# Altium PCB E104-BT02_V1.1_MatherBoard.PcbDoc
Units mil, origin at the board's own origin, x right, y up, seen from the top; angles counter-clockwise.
Board outline 2042.36 x 933 mil, 2 copper layers (Top Layer, Bottom Layer); 37 components, 30 nets, 137 pads, 131 vias.
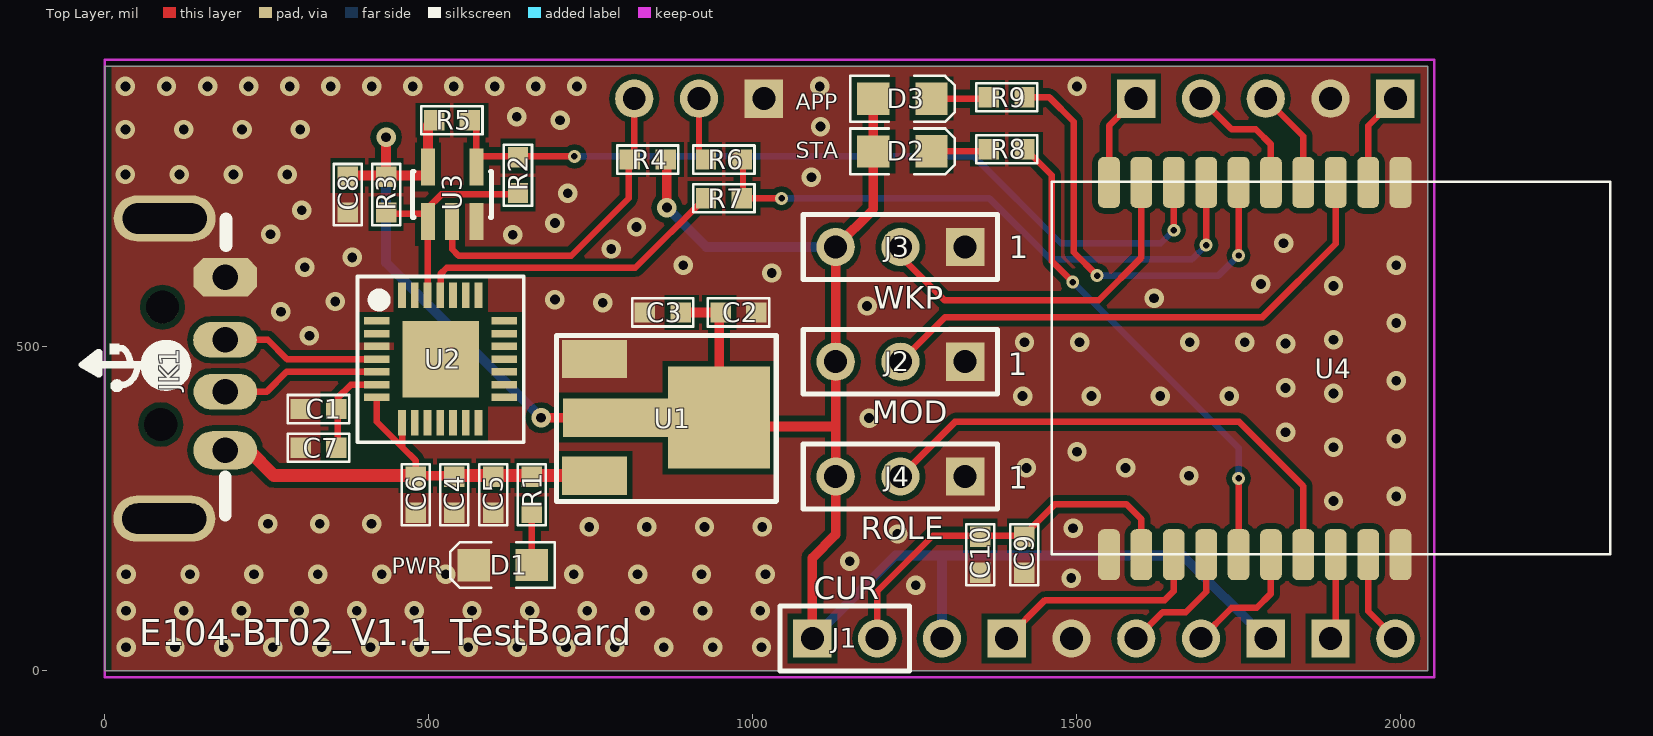
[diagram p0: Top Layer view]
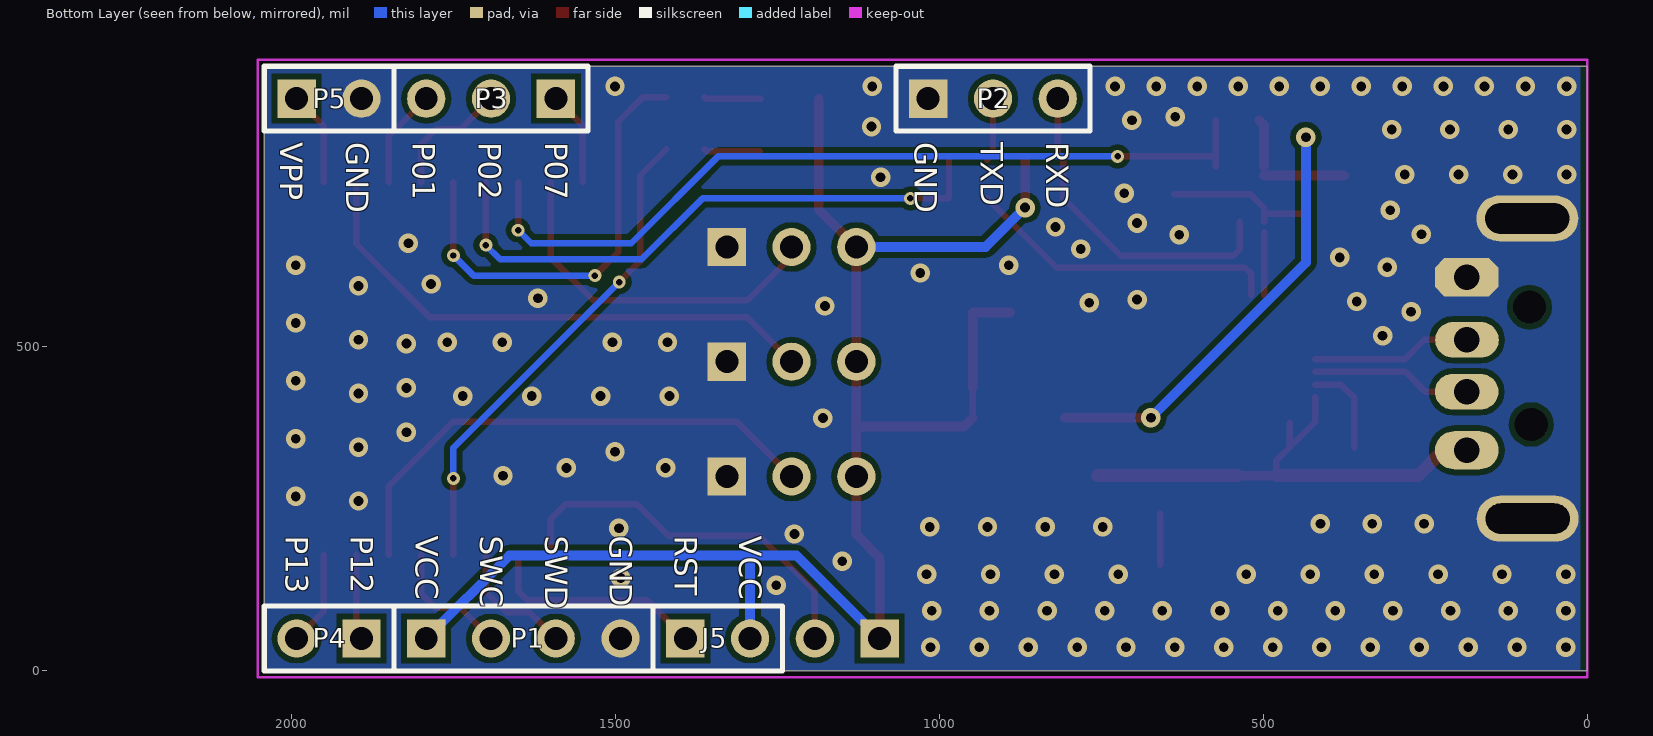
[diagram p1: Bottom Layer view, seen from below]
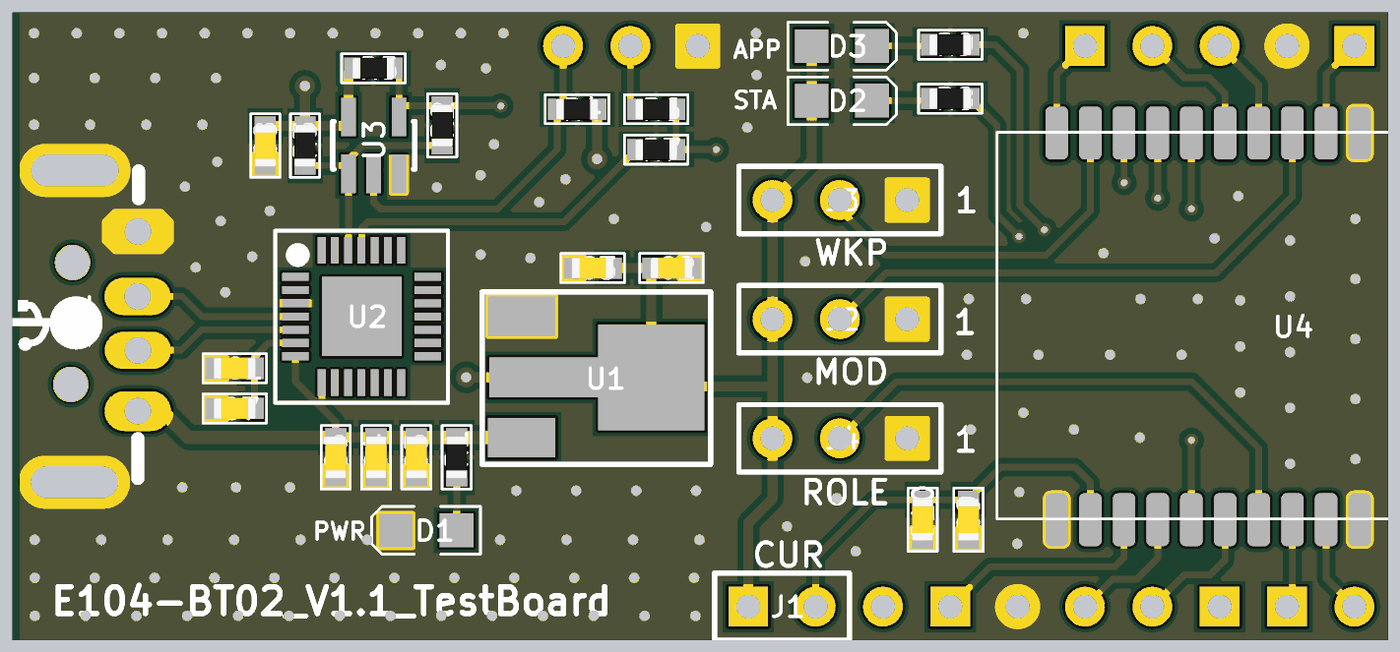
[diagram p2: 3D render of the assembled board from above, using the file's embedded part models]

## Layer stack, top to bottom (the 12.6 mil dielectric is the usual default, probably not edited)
Top Layer: signal copper 1.4
Dielectric: dielectric 12.6, FR-4, Dk 4.8
Bottom Layer: signal copper 1.4

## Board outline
0,0 0,933 2042.36,933 2042.36,0

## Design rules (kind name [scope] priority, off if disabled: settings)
Clearance [All] p1: gap=8.66
MinimumSolderMaskSliver [All] p1: minsoldermaskwidth=1
PolygonConnect [All] p1: connectstyle=Direct reliefconductorwidth=10 reliefentries=4 polygonreliefangle="90 Angle"
RoutingVias [All] p1: holewidth=28 width=50 viastyle="Through Hole" minholewidth=28 minwidth=50 maxholewidth=28 maxwidth=50
SilkToSilkClearance [All] p1: silktosilkclearance=1
SilkscreenOverComponentPads [All] p1: minsilkscreentomaskgap=1
SolderMaskExpansion [All] p1: expansion=4
Width [All] p1: maxlimit=20 minlimit=10 preferedwidth=10
25 further rules are at their usual default settings.

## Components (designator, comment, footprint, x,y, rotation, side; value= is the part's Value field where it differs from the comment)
C1 "10uF" CAP-0603 330.01,404 r180 top
C2 "10uF" CAP-0603 978.48,553 r0 top
C3 "0u1F" CAP-0603 861.48,553 r180 top
C4 "10uF" CAP-0603 539.83,271.6 r270 top
C5 "100nF" CAP-0603 599.66,271.6 r270 top
C6 "0u1F" CAP-0603 480.01,271.6 r270 top
C7 "0u1F" CAP-0603 330.01,344.18 r180 top
C8 "0u1F" CAP-0603 375.36,735 r90 top
C9 "0u1F" CAP-0603 1419.48,179 r270 top
C10 "1uF" CAP-0603 1351.48,179 r270 top
D1 "PWR_LED" LED0805 614.48,163 r180 top
D2 "GRE_LED" LED0805 1231.48,801.82 r0 top
D3 "RED_LED" LED0805 1231.48,883 r0 top
J1 "JMP2" HDR1X2 1142.48,49.68 r0 top
J2 "J_MOD" HDR1X3 1228.48,477 r180 top
J3 "J_WK" HDR1X3 1228.48,654.17 r180 top
J4 "J_ROLE" HDR1X3 1228.48,299.83 r180 top
J5 "J_RST" HDR1X2 1342.48,49.68 r180 bottom
JK1 "USB-A" USB-AG-DIP 136.36,466.4 r0 top
P1 "DBG" HDR1X4 1642.48,49.68 r180 bottom
P2 "EXT_UART" HDR1X3 917.48,883.13 r180 bottom
P3 "PIN0x" HDR1X3 1692.48,883.13 r0 bottom
P4 "PIN1x" HDR1X2 1942.48,49.68 r0 bottom
P5 "VPP" HDR1X2 1942.48,883.13 r180 bottom
R1 "1K" RES-0603 659.48,271.6 r270 top
R2 "NC" RES-0603 638,765 r270 top
R3 "10K" RES-0603 434.36,735 r90 top
R4 "10K" RES-0603 838.36,789.13 r180 top
R5 "NC" RES-0603 536,850 r0 top
R6 "120" RES-0603 955.88,789.13 r0 top
R7 "120" RES-0603 955.88,729.13 r180 top
R8 "1K" RES-0603 1392.48,804.82 r180 top
R9 "1K" RES-0603 1392.48,885 r180 top
U1 "AMS1117-3.3" SOT-223 852.36,391.13 r270 top
U2 "CP2102" QFN28-5X5-P0.5 518.48,481 r0 top
U3 "74LVC1G08" SOT23-5 536.36,693.13 r0 top
U4 "E104-BT02" E104-BT02_V1.1 1775.48,466.4 r270 top

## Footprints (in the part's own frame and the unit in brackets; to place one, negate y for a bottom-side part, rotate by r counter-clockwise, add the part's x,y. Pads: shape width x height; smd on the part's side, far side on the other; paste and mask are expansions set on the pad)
CAP-0603 [mm]
  rect 0.8x0.8 smd: 1(-0.7,0) 2(0.7,0)
  silkscreen extent -1.2,-0.55 1.2,0.55, body extent -0.8,-0.4 0.8,0.4, height 0.92
E104-BT02_V1.1 [mm]
  rrect50% 2x0.85 smd: 1(-7.3,5.715) 2(-7.3,4.445) 3(-7.3,3.175) 4(-7.3,1.905) 5(-7.3,0.635) 6(-7.3,-0.635) 7(-7.3,-1.905) 8(-7.3,-3.175) 9(-7.3,-4.445) 10(-7.3,-5.715) 11(7.3,-5.715) 12(7.3,-4.445) 13(7.3,-3.175) 14(7.3,-1.905) 15(7.3,-0.635) 16(7.3,0.635) 17(7.3,1.905) 18(7.3,3.175) 19(7.3,4.445) 20(7.3,5.715)
  silkscreen extent -7.33,-7.96 7.27,13.94
HDR1X2 [mm] "Connector; Header; 2 Position"
  rect 1.5x1.5 hole 0.9: 1(-1.27,0)
  round 1.5 hole 0.9: 2(1.27,0)
  silkscreen extent -2.54,-1.27 2.54,1.27
HDR1X3 [mm] "Connector; Header; 2 Position"
  rect 1.5x1.5 hole 0.9: 1(-2.54,0)
  round 1.5 hole 0.9: 2(0,0) 3(2.54,0)
  silkscreen extent -3.81,-1.27 3.81,1.27
HDR1X4 [mm] "Connector; Header; 2 Position"
  rect 1.5x1.5 hole 0.9: 1(-3.81,0)
  round 1.5 hole 0.9: 2(-1.27,0) 3(1.27,0) 4(3.81,0)
  silkscreen extent -5.08,-1.27 5.08,1.27
LED0805 [mil]
  rect 50x50 smd: A(-44.9,-0.18) K(44.9,0.18)
  silkscreen extent -80,-36 81,35
QFN28-5X5-P0.5 [mm]
  rect 3x3 smd: 0(0,0)
  rect 1x0.3 smd: 1(-2.5,1.5) 2(-2.5,1) 3(-2.5,0.5) 4(-2.5,0) 5(-2.5,-0.5) 6(-2.5,-1) 7(-2.5,-1.5) 15(2.5,-1.5) 16(2.5,-1) 17(2.5,-0.5) 18(2.5,0) 19(2.5,0.5) 20(2.5,1) 21(2.5,1.5)
  rect 0.3x1 smd: 8(-1.51,-2.5) 9(-1.01,-2.5) 10(-0.51,-2.5) 11(-0.01,-2.5) 12(0.49,-2.5) 13(0.99,-2.5) 14(1.49,-2.5) 22(1.49,2.5) 23(0.99,2.5) 24(0.49,2.5) 25(-0.01,2.5) 26(-0.51,2.5) 27(-1.01,2.5) 28(-1.51,2.5)
  silkscreen extent -3.26,-3.26 3.26,3.24
RES-0603 [mm]
  rect 0.8x0.8 smd: 1(-0.7,0) 2(0.7,0)
  silkscreen extent -1.2,-0.55 1.2,0.55, body extent -0.8,-0.4 0.8,0.4, height 0.5
SOT23-5 [mm]
  rect 0.55x1.45 smd: 1(-0.95,0) 2(0,0) 3(0.95,0) 4(0.95,2.15) 5(-0.95,2.15)
  silkscreen extent -1.55,0.18 1.55,1.98
SOT-223 [mm]
  rect 1.5x2.54 smd: 1(-2.29,-2.444) 3(2.29,-2.444)
  rect 4x4 smd: 2(0.013,2.444)
  rect 1.5x5.04 smd: 2(0.013,-1.156)
  silkscreen extent -3.21,-3.93 3.3,4.69
USB-AG-DIP [mm]
  oval 2.5x1.5 hole 1: 1(1.26,-3.202)
  oval 2.5x1.4 hole 1: 2(1.266,-0.909) 3(1.254,1.129)
  oct 2.5x1.5 hole 1: 4(1.266,3.581)
  oval 4x1.8 hole 1.2 slot 3.3 at 0 deg: 5(-1.127,-5.886) 6(-1.113,5.886)
  round 1.27 hole 1.3: 7(-1.198,2.41) 8(-1.266,-2.194)
  silkscreen extent -4.36,-5.74 1.29,5.87

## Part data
C1 C2 C3 C4 C5 C6 C7: library part cap0603, "Capacitor"
C8 C9 C10: library part Cap, "0603"
D1 D2 D3: library part LED
J2 J3 J4: library part JMP3
J5: library part JMP2
P1: library part "Header 4H", "Header, 4-Pin, Right Angle"
P2 P3: library part "Header 3H", "Header, 3-Pin, Right Angle"
P4 P5: library part "Header 2H", "Header, 2-Pin, Right Angle"
R1: library part res0603
R2 R3 R4 R5 R6 R7 R8 R9: library part Res2, "0603"

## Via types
v1: diameter 30, hole 15, Top Layer to Bottom Layer, tented both sides, 123 vias
v2: diameter 20, hole 10, Top Layer to Bottom Layer, tented both sides, 8 vias

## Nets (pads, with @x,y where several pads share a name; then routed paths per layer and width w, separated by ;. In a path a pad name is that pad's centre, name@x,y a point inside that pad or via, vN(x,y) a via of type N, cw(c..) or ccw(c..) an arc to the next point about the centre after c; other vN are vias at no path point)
DN: JK1.2 U2.5 | length 212.1
  Top Layer w10: JK1.2@220.48,431 250.48,431 280.79,461.31 U2.5
DP: JK1.3 U2.4 | length 214
  Top Layer w10: JK1.3@218.48,511 251.48,511 281.48,481 U2.4
EXT_RXD: P2.2 R6.1 | length 110.2
  Top Layer w10: R6.1@926.36,789.13 917.48,798 P2.2 P2.2@926.36,874.25
EXT_TXD: P2.3 R4.2 U3.2 | length 513.3
  Top Layer w10: U3.2 536.36,650.64 546.34,640.66 720.27,640.66 808.83,729.22 808.83,789.13 817.48,797.78 P2.3
GND: C1.2 C2.2 C3.2 C4.2 C5.2 C6.2 C7.2 C8.1 C9.2 C10.2 D1.K J2.1 J3.1 J4.1 JK1.4 JK1.5 JK1.6 P1.4 P2.1 P5.2 U1.1 U2.3 U3.3 U4.1 U4.11 U4.20
  other v1: 33,36 108.46,36 183.92,36 259.38,36 334.85,36 410.31,36 485.77,36 561.23,36 636.69,36 712.15,36 787.61,36 863.07,36 938.54,36 1014,36 33,92.5 122,92.5 211,92.5 300,92.5 389,92.5 478,92.5 567,92.5 656,92.5 745,92.5 834,92.5 923,92.5 1012,92.5 1252,132 1492,143 33,149 131.7,149 230.4,149 329.1,149 427.8,149 526.5,149 723.9,149 822.6,149 921.3,149 1020,149 1150,169 1224,211 1495,220 748,222 837,222 926,222 1015,222 252,227 332,227 412,227 1897,262 1994,269 1674,301 1423,313 1576,313 1501,338 1897,345 1994,358.25 1823,368 1180,390 1417,424 1523.33,424 1629.67,424 1736,424 1897,428 1823,436.5 1994,447.5 1823,505 1420,507 1505,507 1675,507 1760,507 1897,511 316,517 1994,536.75 272,554 1177,563 769,568 356,570 695,573 1620,575 1897,594 1785,597 1030,614 309,623 893,626 1994,626 382,638 782,651 1820,660 630,673 256,674 821,685 695,691 304,711 715,737 1091,762 32,766 115.33,766 198.67,766 282,766 32,835.5 122,835.5 212,835.5 302,835.5 1105,840 703,850 636,855 32,902 95.36,902 158.73,902 222.09,902 285.45,902 348.82,902 412.18,902 475.55,902 538.91,902 602.27,902 665.64,902 729,902 1104,902 1501,902
NetD1_A: D1.A R1.2 | length 78.9
  Top Layer w10: D1.A 659.48,163.28 R1.2@659.48,242.07
NetD2_K: D2.K R8.2 | length 86.6
  Top Layer w10: D2.K@1277.48,802 1360.13,802 R8.2@1362.95,804.82
NetD3_K: D3.K R9.2 | length 87.3
  Top Layer w10: D3.K 1361.13,883.18 R9.2@1362.95,885
P00_MOD: J2.2 U4.3 | length 842.2
  Top Layer w10: J2.2 1297.48,546 1787.48,546 1900.48,659 U4.3
P01: P3.3 U4.4 | length 153.3
  Top Layer w10: P3.3 1850.48,825.13 U4.4
P02: P3.2 U4.5 | length 196
  Top Layer w10: P3.2 1739.61,836 1777,836 1800.48,812.52 U4.5
P03_APP: R9.1 U4.6 | length 686
  Top Layer w10: R9.1@1422.01,885 1458.48,885 1496,847.48 1496,646 v2(1532,610) ; v2(1750.48,641) U4.6
  Bottom Layer w10: v2(1532,610) 1719.48,610 v2(1750.48,641)
P04_TXD: R6.2 R7.1 U4.7 | length 920
  Top Layer w10: R6.2@985.41,789.13 985.41,729.13 v2(1045.13,729.13) ; v2(1700.48,657) U4.7
  Bottom Layer w10: v2(1045.13,729.13) 1365.87,729.13 1460,635 1678.48,635 v2(1700.48,657)
P05_RXD: R2.1 R5.2 U3.4 U4.8 | length 1286.9
  Top Layer w10: R5.2@573.53,850 573.76,849.77 U3.4 ; U3.4@573.76,794.53 638,794.53 724.47,794.53 v2(725,794) ; v2(1650.48,680) U4.8
  Bottom Layer w10: v2(725,794) 1342,794 1476,660 1630.48,660 v2(1650.48,680)
P06_WK: J3.2 U4.9 | length 557.5
  Top Layer w10: J3.2 1228.48,640 1296.48,572 1534.48,572 1600.48,638 U4.9
P07: P3.1 U4.10 | length 146.7
  Top Layer w10: U4.10 1550.48,841.13 P3.1
P10_SWD: P1.3 U4.14 | length 195
  Top Layer w10: P1.3 1633.14,90.34 1668.82,90.34 1700.48,122 U4.14
P11_STETE: R8.1 U4.15 | length 761.9
  Top Layer w10: R8.1@1422.01,804.82 1462,764.83 1462,632.48 v2(1494.48,600) ; U4.15 v2(1750.48,297)
  Bottom Layer w10: v2(1494.48,600) 1750.48,344 v2(1750.48,297)
P12: P4.1 U4.18 | length 132.6
  Top Layer w10: P4.1 1900.48,57.68 U4.18
P13: P4.2 U4.19 | length 146.7
  Top Layer w10: U4.19 1950.48,91.68 P4.2
P14_ROLE: J4.2 U4.17 | length 803.9
  Top Layer w10: J4.2 1312.65,384 1751.48,384 1850.48,285 U4.17
P15_SWC: P1.2 U4.16 | length 218
  Top Layer w10: P1.2 1739.8,97 1778.48,97 1800.48,119 U4.16 U4.16@1800.48,157.68
RESET_H: J5.1 U4.13 | length 344.4
  Top Layer w10: J5.1 1451.8,109 1636.48,109 1650.48,123 U4.13
TTL_RXD: R7.2 U2.25 | length 489.2
  Top Layer w10: U2.25@518.48,579.43 518.48,612.48 528,622 819.23,622 R7.2@926.35,729.13
TTL_TXD: R2.2 R3.1 U2.26 U3.1 | length 348.7
  Top Layer w10: R3.1@434.36,705.47 495.3,705.47 U3.1@498.8,708.97 ; U2.26@498.8,579.43 U3.1@498.8,677.13 ; U3.1@498.95,709.13 U3.1@498.8,708.97 ; R2.2@638,735.33 519.87,735.33 498.8,714.26 498.8,693.13 U3.1@498.8,708.97
V3.3: C2.1 C3.1 C8.2 D2.A D3.A J1.1 J2.3 J3.3 J4.3 J5.2 P1.1 R3.2 R4.1 R5.1 U1.2 U3.5 | length 3496.5
  Top Layer w10: C3.1@891.01,553 C3.1@891.38,552.62 ; U1.2@948.58,390.62 U1.2@948.58,437
  Top Layer w15: C8.2@375.36,764.53 R3.2@434.36,764.53 ; v1(434.36,823.64) R3.2@434.36,764.53 ; U3.5 498.95,842.48 R5.1@506.47,850 ; U3.5@499,764.53 R3.2@434.36,764.53 ; v1(673.62,390.62) U1.2@806.85,390.62 ; v1@867.88,715 R4.1@867.88,789.13 ; C3.1@891.01,553 948.2,553 948.58,552.62 U1.2@948.58,437 ; U1.2@948.58,390.62 962.2,377 1128.48,377 ; J1.1 1092.48,174 1128.48,210 J4.3 1128.48,377 ; D3.A D2.A 1186.58,712.27 J3.3 J2.3 1128.48,377
  Bottom Layer w15: v1(434.36,823.64) 434.36,629.88 v1(673.62,390.62) ; v1(868,715) 928.83,654.17 J3.3 ; J1.1 1220.8,178 1294,178 ; J5.2 1292.48,176.48 1294,178 ; P1.1 1664.16,178 1294,178
VBUS: C4.1 C5.1 C6.1 JK1.1 R1.1 U1.3 U2.7 U2.8 | length 889.3
  Top Layer w10: U2.7 420.06,384.42 459.43,345.05 ; U2.8@459.43,382.58 459.43,345.05 ; C6.1@480.01,301.13 480.01,324.48 459.43,345.05 ; U1.3@755.98,301.13 U1.3
  Top Layer w15: C6.1@480.01,301.13 539.83,301.13 599.66,301.13 R1.1@659.48,301.13
  Top Layer w20: JK1.1 222.27,340.34 261.48,301.13 C6.1@480.01,301.13 ; C4.1@539.83,301.13 599.66,301.13 659.48,301.13 U1.3@755.98,301.13
VCC: C9.1 C10.1 J1.2 U4.12 | length 601.1
  Top Layer w10: J1.2 1192.48,122.48 1278.53,208.53 1418.53,208.53 1467,257 1577.48,257 1600.48,234 U4.12
VDD: C1.1 C7.1 U2.6 | length 145.9
  Top Layer w10: C7.1@359.54,344.17 359.54,421.05 380.11,441.63 U2.6
VPP: P5.1 U4.2 | length 146.7
  Top Layer w10: U4.2 1950.48,841.13 P5.1
pads on no net: JK1.7 JK1.8 U2.0 U2.1 U2.2 U2.9 U2.10 U2.11 U2.12 U2.13 U2.14 U2.15 U2.16 U2.17 U2.18 U2.19 U2.20 U2.21 U2.22 U2.23 U2.24 U2.27 U2.28

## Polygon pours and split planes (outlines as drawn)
GND on Top Layer "Top Layer-No Net" (solid, remove dead copper, pour order 1000): 0,933 2042.36,933 2042.36,0 0,0
GND on Bottom Layer "Top Layer-No Net" (solid, remove dead copper, pour order 1001): 0,933 2042.36,933 2042.36,0 0,0

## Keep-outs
Keep-Out Layer:
  lines w3.94: 0,-10 0,943 2052.36,943 2052.36,-10 0,-10

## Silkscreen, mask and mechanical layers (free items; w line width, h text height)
Top Overlay:
  text "APP" at 1067,866 h25
  text "STA" at 1067,791 h25
  text "1" at 1396,637 h35
  text "WKP" at 1187,559 h35
  text "1" at 1394,456 h35
  text "MOD" at 1185,382 h35
  text "1" at 1395,281 h35
  text "ROLE" at 1167,203 h35
  text "PWR" at 443,150 h25
  text "CUR" at 1095,110 h35
  text "E104-BT02_V1.1_TestBoard" at 53,39 h40
Bottom Overlay:
  text "RXD" at 835,815.66 h35 r90
  text "TXD" at 936.5,815.66 h35 r90
  text "GND" at 1038,815.66 h35 r90
  text "P07" at 1609,815.66 h35 r90
  text "P02" at 1711.25,815.66 h35 r90
  text "P01" at 1813.5,815.66 h35 r90
  text "GND" at 1915.75,815.66 h35 r90
  text "VPP" at 2018,815.66 h35 r90
  text "VCC" at 1309,208 h35 r90
  text "RST" at 1409,208 h35 r90
  text "GND" at 1509,208 h35 r90
  text "SWD" at 1609,208 h35 r90
  text "SWC" at 1709,208 h35 r90
  text "VCC" at 1809,208 h35 r90
  text "P12" at 1909,208 h35 r90
  text "P13" at 2009,208 h35 r90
